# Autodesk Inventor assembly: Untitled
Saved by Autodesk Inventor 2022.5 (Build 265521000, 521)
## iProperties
Created: 2024-12
Part Number: Untitled
Document SubType Name: Assembly
Designer: AdminForWorker
Title: Untitled v1
Author: AdminForWorker
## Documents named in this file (6)
- c:\worker\convert-fusion-r05-cosv3\tmp\job-1\35\temp\files\545dca92-a972-481a-9197-dd1a1176500e\b7772d58-0924-456d-9278-ec2860b0e9db.iam
- c:\worker\convert-fusion-r05-cosv3\tmp\job-1\35\temp\files\545dca92-a972-481a-9197-dd1a1176500e\raspberry_pi_3_b_plus v1.iam
- c:\worker\convert-fusion-r05-cosv3\tmp\job-1\35\temp\files\545dca92-a972-481a-9197-dd1a1176500e\TCS230-TCS3200 v1.ipt
- c:\worker\convert-fusion-r05-cosv3\tmp\job-1\35\temp\files\545dca92-a972-481a-9197-dd1a1176500e\tcs34725_rgb_sensor v1.ipt
- c:\worker\convert-fusion-r05-cosv3\tmp\job-1\35\temp\files\545dca92-a972-481a-9197-dd1a1176500e\Interface PH v1.ipt
- c:\worker\convert-fusion-r05-cosv3\tmp\job-1\35\temp\files\545dca92-a972-481a-9197-dd1a1176500e\Part134.ipt
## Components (5 placed, 5 different names)
1. raspberry_pi_3_b_plus v1:1 [sub-assembly]
2. TCS230-TCS3200 v1:1
3. tcs34725_rgb_sensor v1:1
4. Interface PH v1:1
5. Part134
